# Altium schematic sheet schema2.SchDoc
size A3; ApprovedBy: CdB; CheckedBy: CdB; DrawnBy: RT; Engineer: CdB; Organization: Faber Electronics B.V.; Address1: Th. Dobbeweg 1,; Address2: 6883 GN Velp,; Address3: Netherlands; Address4: T: 026-38 46 800; DocumentNumber: 2; Revision: 2.1.4; SheetNumber: 2; SheetTotal: 6; Status: Final; PageSetup: Record=PageOptions|CenterHorizontal=True|CenterVertical=True|PrintScale=1.01|XCorrection=1.00|YCorrection=1.00|PrintKind=1|BorderSize=5000000|LeftOffset=0|BottomOffset=0|Orientation=2|PaperLength=1000|PaperWidth=1000|Scale=100|PaperSource=7|PrintQuality=1200|MediaType=1|DitherType=10|PaperKind=A3 (297 x 420mm)|PrintScaleMode=1
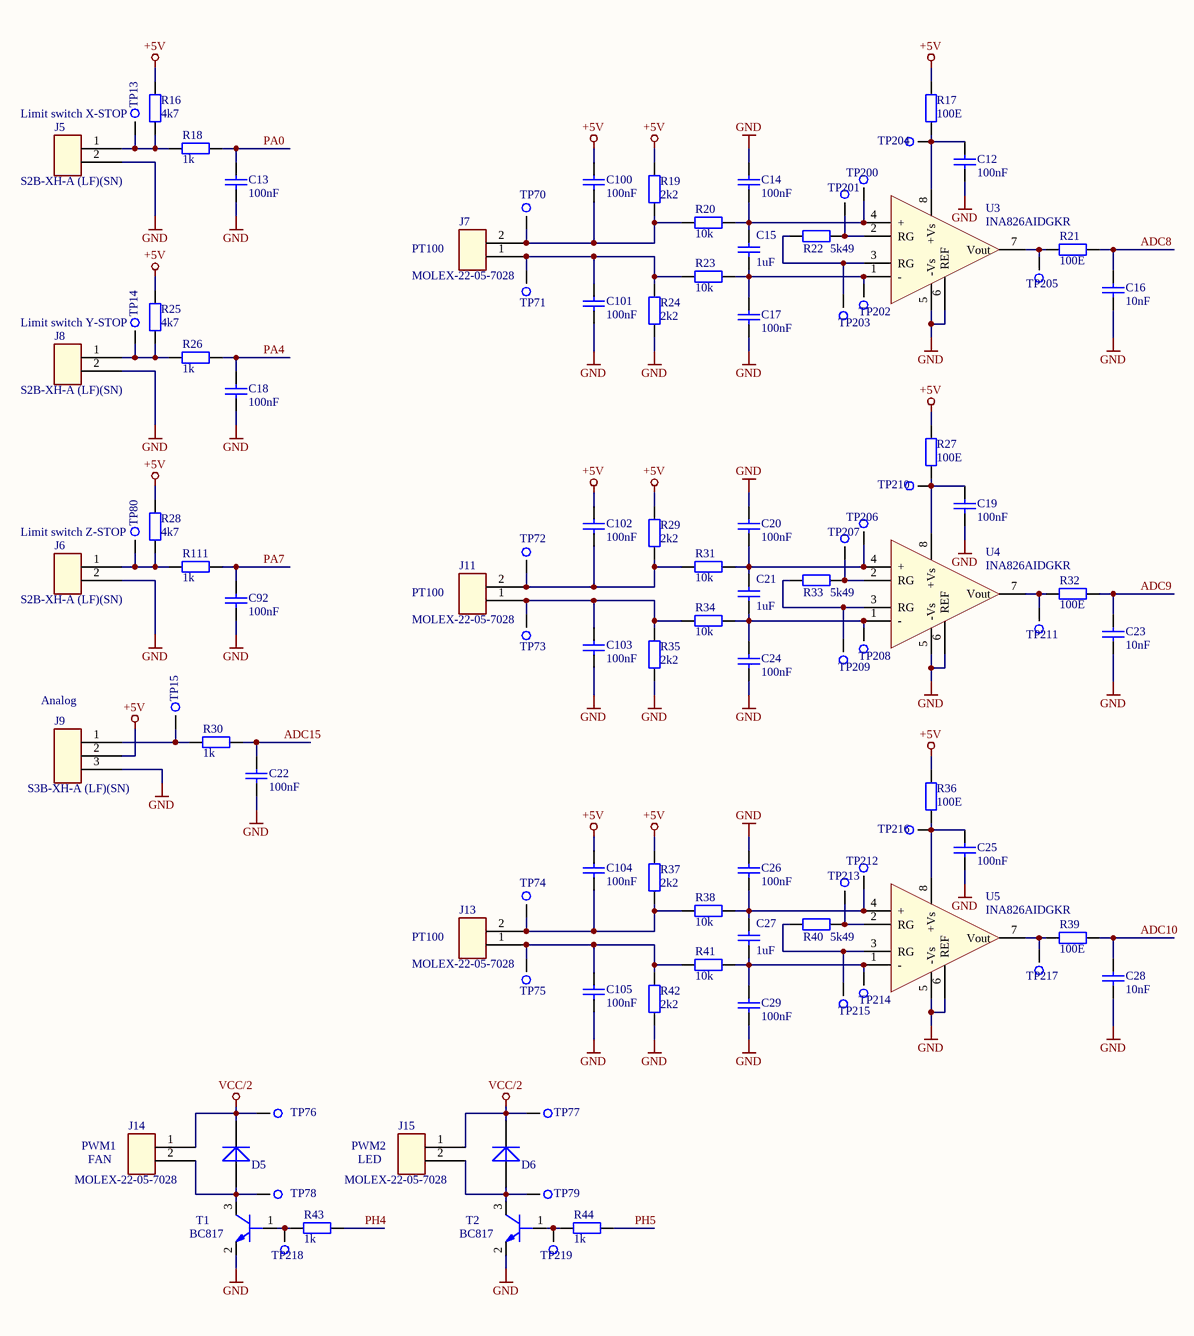
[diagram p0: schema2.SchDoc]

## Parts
C12  100nF  [C0603]
C13  100nF  [C0603]
C14  100nF  [C0603]
C15  1uF  [C0603]
C16  10nF  [C0603]
C17  100nF  [C0603]
C18  100nF  [C0603]
C19  100nF  [C0603]
C20  100nF  [C0603]
C21  1uF  [C0603]
C22  100nF  [C0603]
C23  10nF  [C0603]
C24  100nF  [C0603]
C25  100nF  [C0603]
C26  100nF  [C0603]
C27  1uF  [C0603]
C28  10nF  [C0603]
C29  100nF  [C0603]
C92  100nF  [C0603]
C100  100nF  [C0603]
C101  100nF  [C0603]
C102  100nF  [C0603]
C103  100nF  [C0603]
C104  100nF  [C0603]
C105  100nF  [C0603]
D5  S1G  [DO214AC (SMA)]  (value not drawn)
D6  S1G  [DO214AC (SMA)]  (value not drawn)
J5  S2B-XH-A (LF)(SN)  [S2B-XH-A (LF)(SN)]
J6  S2B-XH-A (LF)(SN)  [S2B-XH-A (LF)(SN)]
J7  MOLEX-22-05-7028  [MOLEX-22-05-7028]
J8  S2B-XH-A (LF)(SN)  [S2B-XH-A (LF)(SN)]
J9  S3B-XH-A (LF)(SN)  [S3B-XH-A (LF)(SN)]
J11  MOLEX-22-05-7028  [MOLEX-22-05-7028]
J13  MOLEX-22-05-7028  [MOLEX-22-05-7028]
J14  MOLEX-22-05-7028  [MOLEX-22-05-7028]
J15  MOLEX-22-05-7028  [MOLEX-22-05-7028]
R16  4k7  [R0603]
R17  100E  [R0603]
R18  1k  [R0603]
R19  2k2  [R0603]
R20  10k  [R0603]
R21  100E  [R0603]
R22  5k49  [R0603]
R23  10k  [R0603]
R24  2k2  [R0603]
R25  4k7  [R0603]
R26  1k  [R0603]
R27  100E  [R0603]
R28  4k7  [R0603]
R29  2k2  [R0603]
R30  1k  [R0603]
R31  10k  [R0603]
R32  100E  [R0603]
R33  5k49  [R0603]
R34  10k  [R0603]
R35  2k2  [R0603]
R36  100E  [R0603]
R37  2k2  [R0603]
R38  10k  [R0603]
R39  100E  [R0603]
R40  5k49  [R0603]
R41  10k  [R0603]
R42  2k2  [R0603]
R43  1k  [R0603]
R44  1k  [R0603]
R111  1k  [R0603]
T1  BC817  [SOT23]
T2  BC817  [SOT23]
TP13  Testpoint  [Testpoint]  (value not drawn)
TP14  Testpoint  [Testpoint]  (value not drawn)
TP15  Testpoint  [Testpoint]  (value not drawn)
TP70  Testpoint  [Testpoint]  (value not drawn)
TP71  Testpoint  [Testpoint]  (value not drawn)
TP72  Testpoint  [Testpoint]  (value not drawn)
TP73  Testpoint  [Testpoint]  (value not drawn)
TP74  Testpoint  [Testpoint]  (value not drawn)
TP75  Testpoint  [Testpoint]  (value not drawn)
TP76  Testpoint  [Testpoint]  (value not drawn)
TP77  Testpoint  [Testpoint]  (value not drawn)
TP78  Testpoint  [Testpoint]  (value not drawn)
TP79  Testpoint  [Testpoint]  (value not drawn)
TP80  Testpoint  [Testpoint]  (value not drawn)
TP200  Testpoint 1.6mm  [Testpoint 1.6mm]  (value not drawn)
TP201  Testpoint 1.6mm  [Testpoint 1.6mm]  (value not drawn)
TP202  Testpoint 1.6mm  [Testpoint 1.6mm]  (value not drawn)
TP203  Testpoint 1.6mm  [Testpoint 1.6mm]  (value not drawn)
TP204  Testpoint 1.6mm  [Testpoint 1.6mm]  (value not drawn)
TP205  Testpoint 1.6mm  [Testpoint 1.6mm]  (value not drawn)
TP206  Testpoint 1.6mm  [Testpoint 1.6mm]  (value not drawn)
TP207  Testpoint 1.6mm  [Testpoint 1.6mm]  (value not drawn)
TP208  Testpoint 1.6mm  [Testpoint 1.6mm]  (value not drawn)
TP209  Testpoint 1.6mm  [Testpoint 1.6mm]  (value not drawn)
TP210  Testpoint 1.6mm  [Testpoint 1.6mm]  (value not drawn)
TP211  Testpoint 1.6mm  [Testpoint 1.6mm]  (value not drawn)
TP212  Testpoint 1.6mm  [Testpoint 1.6mm]  (value not drawn)
TP213  Testpoint 1.6mm  [Testpoint 1.6mm]  (value not drawn)
TP214  Testpoint 1.6mm  [Testpoint 1.6mm]  (value not drawn)
TP215  Testpoint 1.6mm  [Testpoint 1.6mm]  (value not drawn)
TP216  Testpoint 1.6mm  [Testpoint 1.6mm]  (value not drawn)
TP217  Testpoint 1.6mm  [Testpoint 1.6mm]  (value not drawn)
TP218  Testpoint 1.6mm  [Testpoint 1.6mm]  (value not drawn)
TP219  Testpoint 1.6mm  [Testpoint 1.6mm]  (value not drawn)
U3  INA826AIDGKR  [TSOP65P490X110-8N (MSOP8)]
U4  INA826AIDGKR  [TSOP65P490X110-8N (MSOP8)]
U5  INA826AIDGKR  [TSOP65P490X110-8N (MSOP8)]

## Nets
+5V: C100.2 C102.2 C104.2 J9.2 R16.2 R17.1 R19.1 R25.2 R27.1 R28.2 R29.1 R36.1 R37.1
GND: C12.1 C13.1 C14.2 C16.1 C17.1 C18.1 C19.1 C20.2 C22.1 C23.1 C24.1 C25.1 C26.2 C28.1 C29.1 C92.1 C101.1 C103.1 C105.1 J5.2 J6.2 J8.2 J9.3 R24.1 R35.1 R42.1 T1.2(EMITTER) T2.2(EMITTER) U3.5(-Vs) U3.6(REF) U4.5(-Vs) U4.6(REF) U5.5(-Vs) U5.6(REF)
VCC/2: D5.2(K) D6.2(K) J14.1 J15.1 TP76.1 TP77.1
ADC8: C16.2 R21.2
ADC9: C23.2 R32.2
ADC10: C28.2 R39.2
ADC15: C22.2 R30.2
PA0: C13.2 R18.2
PA4: C18.2 R26.2
PA7: C92.2 R111.2
PH4: R43.1
PH5: R44.1
NetC12_2: C12.2 R17.2 TP204.1 U3.8(+Vs)
NetC14_1: C14.1 C15.2 R20.2 TP200.1 U3.4(+)
NetC15_1: C15.1 C17.2 R23.2 TP202.1 U3.1(-)
NetC19_2: C19.2 R27.2 TP210.1 U4.8(+Vs)
NetC20_1: C20.1 C21.2 R31.2 TP206.1 U4.4(+)
NetC21_1: C21.1 C24.2 R34.2 TP208.1 U4.1(-)
NetC25_2: C25.2 R36.2 TP216.1 U5.8(+Vs)
NetC26_1: C26.1 C27.2 R38.2 TP212.1 U5.4(+)
NetC27_1: C27.1 C29.2 R41.2 TP214.1 U5.1(-)
NetC100_1: C100.1 J7.2 R19.2 R20.1 TP70.1
NetC101_2: C101.2 J7.1 R23.1 R24.2 TP71.1
NetC102_1: C102.1 J11.2 R29.2 R31.1 TP72.1
NetC103_2: C103.2 J11.1 R34.1 R35.2 TP73.1
NetC104_1: C104.1 J13.2 R37.2 R38.1 TP74.1
NetC105_2: C105.2 J13.1 R41.1 R42.2 TP75.1
NetD5_1: D5.1(A) J14.2 T1.3(COLLECTOR) TP78.1
NetD6_1: D6.1(A) J15.2 T2.3(COLLECTOR) TP79.1
NetJ5_1: J5.1 R16.1 R18.1 TP13.1
NetJ6_1: J6.1 R28.1 R111.1 TP80.1
NetJ8_1: J8.1 R25.1 R26.1 TP14.1
NetJ9_1: J9.1 R30.1 TP15.1
NetR21_1: R21.1 TP205.1 U3.7(Vout)
NetR22_1: R22.1 TP201.1 U3.2(RG)
NetR22_2: R22.2 TP203.1 U3.3(RG)
NetR32_1: R32.1 TP211.1 U4.7(Vout)
NetR33_1: R33.1 TP207.1 U4.2(RG)
NetR33_2: R33.2 TP209.1 U4.3(RG)
NetR39_1: R39.1 TP217.1 U5.7(Vout)
NetR40_1: R40.1 TP213.1 U5.2(RG)
NetR40_2: R40.2 TP215.1 U5.3(RG)
NetR43_2: R43.2 T1.1(BASE) TP218.1
NetR44_2: R44.2 T2.1(BASE) TP219.1

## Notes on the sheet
- (near TP13) Limit switch X-STOP
- (near J7) PT100
- (near TP14) Limit switch Y-STOP
- (near TP80) Limit switch Z-STOP
- (near J11) PT100
- (near J9) Analog
- (near J13) PT100
- (near J14) PWM1
- (near J14) FAN
- PWM2
- LED

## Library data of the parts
C12-C14 C17-C20 C22 C24-C26 C29 C92 C100-C105 = Library_CAP-0002: RO X7R 100nF 10% 50V 0603; Faber ItemCode: 45068500
C15 C21 C27 = Library_CAP-0006: RO X5R 1uF 10% 10V 0603; Faber ItemCode: 36310600
C16 C23 C28 = Library_CAP-0007: RO X7R 10nF 10% 50V 0603; Faber ItemCode: 36270400
D5 D6 = Library_DIO-0001: RO DIODE S1G DO-214AC; Faber ItemCode: 32284000; Info: Fast Rectifiers 1A 400V
J5 J6 J8 = Library_CON-0004: RO CONN PR 2p HKS S2B-XH-A (LF)(SN) JST; Mfg: JST (JAPAN SOLDERLESS TERMINALS); Faber ItemCode: 36926700
J7 J11 J13-J15 = Library_CON-0006: RO CONN PR 2p HKS 22-05-7028 MOLEX; Info: 2.54mm Pitch KK® Wire-to-Board Header, Right Angle, with Friction Lock, 2 Circuits; Faber ItemCode: 36926400
J9 = Library_CON-0020: RO CONN PR 3p HKS S3B-XH-A (LF)(SN) JST; Faber ItemCode: 36948200; Mfg: JST (JAPAN SOLDERLESS TERMINALS)
R16 R25 R28 = Library_RES-0002: RO RES 4k70 1% 0,063W  0603; Faber ItemCode: 36257400
R17 R21 R27 R32 R36 R39 = Library_RES-0006: RO RES 100E 1% 0,063W  0603; Faber ItemCode: 32338800
R18 R26 R30 R43 R44 R111 = Library_RES-0004: RO RES 1k0 1% 0,1W  0603; Faber ItemCode: 34637900
R19 R24 R29 R35 R37 R42 = Library_RES-0010: RO RES 2k2 0,1% 0,063W 25ppm 0603; Mfg: TE CONNECTIVITY / NEOHM; Mfg code: CPF0603B2K2E1; Faber ItemCode: 36926600
R20 R23 R31 R34 R38 R41 = Library_RES-0001: RO RES 10k0 1% 0,063W  0603; Faber ItemCode: 36084500
R22 R33 R40 = Library_RES-0011: RO RES 5K49 0,1% 0,063W 25ppm 0603; Mfg: WELWYN; Mfg code: PCF0603R 5K49B.T1; Faber ItemCode: 36926200
T1 T2 = Library_TRA-0001: RO TRANS BC817-25  SOT-23; Faber ItemCode: 30828000; Info: 45 V, 500 mA NPN general-purpose transistors
TP13-TP15 TP70-TP80 = Library_MISC-0001: Info: Testpoint, 2mm, round
TP200-TP219 = Testpoint 1.6mm: ID: Library_MISC-0001
U3-U5 = Library_ICS-0003: RO IC INA826AIDGKR MSOP-8 TI; Mfg: Texas Instruments; Info: Precision, 200-µA Supply Current, 2.7-V to 36-V Supply Instrumentation Amplifier with Rail-to-Rail Output; Faber ItemCode: 36926300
